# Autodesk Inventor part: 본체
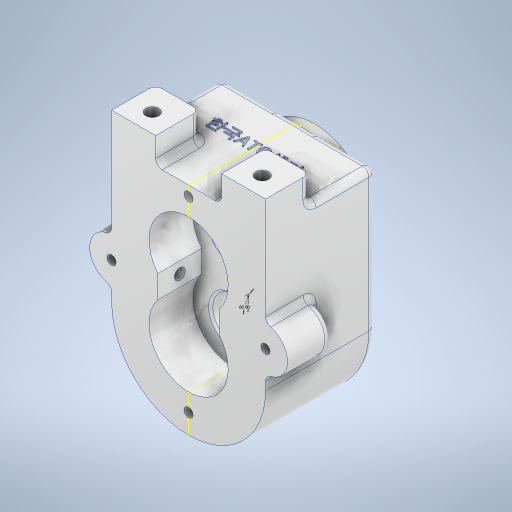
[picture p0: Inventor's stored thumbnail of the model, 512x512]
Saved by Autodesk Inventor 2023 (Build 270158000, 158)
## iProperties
Created: 2024-03
Part Number: 본체
Material: 알루미늄 6061
Document SubType Name: Modeling
Designer: asung
Density: 2.7 g/cm^3
Appearance: 알루미늄 - 평지
Author: asung
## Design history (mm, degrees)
sketch "스케치1"
  geometry: L1 (-35, 0)-(-35, 63.5); L2 (35, 0)-(35, 63.5); L3 (-35, 63.5)-(35, 63.5); A1 r 35 centre (0, 0) between (-35, 0) and (35, 0); 3 further points
  constraints: 6 end point, 2 point on circle, 2 tangent, 2 vertical, 1 centre point, 1 coincident, 1 horizontal
  dimensions: "d0" = 70 diameter of A1; "d2" = 70 distance of L3.start L3.end; "d3" = 63.5 distance from line of point (0, 0) L3; "d4" = 0 distance from line of L2.end L3; "d5" = 0 distance from line of L3.end L2; "d6" = 0 distance from line of L1.end L3
extrude "돌출1" new body sketch "스케치1" distance "d7" = 50; taper "d8" = 0 deg
sketch "스케치2"
  geometry: L1 (-35, 0)-(-35, 63.5) reference; L2 (-35, 63.5)-(35, 63.5) reference; L3 (35, 63.5)-(35, 0) reference; L4 (0, 0)-(0, 33); L5 (14, 11.314)-(14, 21.686); L6 (-14, 11.314)-(-14, 21.686); L7 (-35, 0)-(-35, 63.5) reference; L8 (-35, 63.5)-(35, 63.5) reference; L9 (35, 63.5)-(35, 0) reference; L10 (-25, 8)-(-25, 63.5); L11 (25, 8)-(25, 63.5); L12 (-17, 0)-(17, 0); A1 r 35 centre (0, 0) between (-35, 0) and (35, 0) reference; A2 r 18 centre (0, 0) between (-14, 11.314) and (14, 11.314); A3 r 18 centre (0, 33) between (14, 21.686) and (-14, 21.686); A4 r 35 centre (0, 0) between (-35, 0) and (35, 0) reference; A5 r 8 centre (-17, 8) between (-25, 8) and (-17, 0); A6 r 8 centre (17, 8) between (17, 0) and (25, 8); 1 further point
  constraints: 12 end point, 8 point on circle, 4 centre point, 4 parallel, 4 tangent, 2 coincident, 2 point on line, 1 horizontal, 1 vertical
  dimensions: "d9" = 36 diameter of A2; "d10" = 33 distance of L4.start L4.end; "d11" = 36 diameter of A3; "d12" = 14 distance between parallel lines of L4 L5; "d13" = 14 distance between parallel lines of L4 L6; "d137" = 25 distance between parallel lines of L4 L10; "d138" = 25 distance between parallel lines of L4 L11; "d139" = 8 radius of A5; "d140" = 8 radius of A6
extrude "돌출2" cut sketch "스케치2" distance "d14" = 20; taper "d15" = 0 deg
sketch "스케치4"
  geometry: L1 (-14, 21.686)-(-14, 11.314) reference; L2 (14, 11.314)-(14, 21.686) reference; L3 (-35, 0)-(-35, 63.5) reference; L4 (-35, 63.5)-(35, 63.5) reference; L5 (35, 63.5)-(35, 0) reference; L6 (-35, 63.5)-(-15, 63.5); L7 (-15, 63.5)-(-15, 75.5); L8 (-15, 75.5)-(-35, 75.5); L9 (-35, 75.5)-(-35, 63.5); L10 (35, 63.5)-(15, 63.5); L11 (15, 63.5)-(15, 75.5); L12 (15, 75.5)-(35, 75.5); L13 (35, 75.5)-(35, 63.5); A1 r 18 centre (0, 33) between (14, 21.686) and (-14, 21.686) reference; A2 r 18 centre (0, 0) between (-14, 11.314) and (14, 11.314) reference; A3 r 35 centre (0, 0) between (-35, 0) and (35, 0) reference; 5 further points
  constraints: 16 end point, 4 parallel, 2 horizontal, 2 midpoint, 2 perpendicular
  dimensions: "d16" = 30 distance of L11.end L7.end; "d20" = 20 distance of L7.end L8.end; "d21" = 20 distance of L12.end L11.end; "d22" = 12 distance between parallel lines of L4 L12
extrude "돌출3" join sketch "스케치4" distance "d23" = 20; taper "d24" = 0 deg
fillet "모깎기1" dims "d25" = 3
fillet "모깎기2" dims "d26" = 3
fillet "모깎기3" dims "d27" = 3
sketch "스케치5"
  geometry: L1 (-35, 0)-(-35, 75.5) reference; L2 (-35, 75.5)-(-15, 75.5) reference; L3 (-15, 75.5)-(-15, 66.5) reference; L4 (-12, 63.5)-(12, 63.5) reference; L5 (15, 66.5)-(15, 75.5) reference; L6 (15, 75.5)-(35, 75.5) reference; L7 (35, 75.5)-(35, 0) reference; L8 (-14, 21.686)-(-14, 11.314) reference; L9 (14, 11.314)-(14, 21.686) reference; L10 (0, 0)-(0, -26); L11 (-14, 16.5)-(14, 16.5); L12 (0, 33)-(0, 0); L13 (-35, 33)-(-35, 0); L14 (35, 33)-(35, 0); A1 r 3 centre (-12, 66.5) between (-15, 66.5) and (-12, 63.5) reference; A2 r 3 centre (12, 66.5) between (12, 63.5) and (15, 66.5) reference; A3 r 35 centre (0, 0) between (-35, 0) and (35, 0) reference; A4 r 18 centre (0, 33) between (14, 21.686) and (-14, 21.686) reference; A5 r 18 centre (0, 0) between (-14, 11.314) and (14, 11.314) reference; A6 r 10 centre (-35, 16.5) between (-35, 26.5) and (-35, 6.5); A7 r 10 centre (35, 16.5) between (35, 6.5) and (35, 26.5); 7 further points
  constraints: 10 end point, 6 midpoint, 4 point on circle, 4 point on line, 2 centre point, 2 horizontal alignment, 2 parallel, 2 vertical
  dimensions: "d28" = 26 distance of L10.start L10.end; "d29" = 35 distance between parallel lines of L12 L13; "d30" = 35 distance between parallel lines of L12 L14; "d31" = 10 radius of A6; "d32" = 10 radius of A7
extrude "돌출4" join sketch "스케치5" distance "d33" = 20; taper "d34" = 0 deg
fillet "모깎기4" dims "d35" = 3
fillet "모깎기5" dims "d36" = 3
sketch "스케치6"
  geometry: A1 r 10 centre (35, 16.5) between (37.308, 6.77) and (37.308, 26.23) reference; A2 r 10 centre (-35, 16.5) between (-37.308, 26.23) and (-37.308, 6.77) reference; 3 further points
  constraints: 2 coincident
hole "구멍1" sketch "스케치6" at (35, 16.5), (-35, 16.5) diameter "d37" = 4.134; stored, may be unused: countersink angle "d41" = 90 deg, drill point angle "d43" = 118 deg; dims "d38" = 10, "d39" = 7, "d40" = 3, "d42" = 12
sketch "스케치8"
  geometry: L1 (14, 21.686)-(14, 11.314) reference; L2 (-14, 11.314)-(-14, 21.686) reference; L3 (35, 0)-(35, 3.851) reference; L4 (35, 29.149)-(35, 75.5) reference; L5 (35, 75.5)-(15, 75.5) reference; L6 (15, 75.5)-(15, 66.5) reference; L7 (12, 63.5)-(-12, 63.5) reference; L8 (-15, 66.5)-(-15, 75.5) reference; L9 (-15, 75.5)-(-35, 75.5) reference; L10 (-35, 75.5)-(-35, 29.149) reference; L11 (-35, 3.851)-(-35, 0) reference; L12 (0, 0)-(0, -26); L13 (0, 33)-(0, 59); C1 r 2.067 at (35, 16.5) reference; C2 r 2.067 at (-35, 16.5) reference; A1 r 18 centre (0, 33) between (14, 21.686) and (-14, 21.686) reference; A2 r 18 centre (0, 0) between (-14, 11.314) and (14, 11.314) reference; A3 r 35 centre (0, 0) between (-35, 0) and (35, 0) reference; A4 r 3 centre (38, 3.851) between (37.308, 6.77) and (35, 3.851) reference; A5 r 10 centre (35, 16.5) between (37.308, 6.77) and (37.308, 26.23) reference; A6 r 3 centre (38, 29.149) between (35, 29.149) and (37.308, 26.23) reference; A7 r 3 centre (12, 66.5) between (12, 63.5) and (15, 66.5) reference; A8 r 3 centre (-12, 66.5) between (-15, 66.5) and (-12, 63.5) reference; A9 r 3 centre (-38, 29.149) between (-37.308, 26.23) and (-35, 29.149) reference; A10 r 10 centre (-35, 16.5) between (-37.308, 26.23) and (-37.308, 6.77) reference; A11 r 3 centre (-38, 3.851) between (-35, 3.851) and (-37.308, 6.77) reference; 1 further point
  constraints: 4 end point, 2 vertical
  dimensions: "d44" = 26 distance of L12.start L12.end; "d45" = 26 distance of L13.start L13.end
hole "구멍2" sketch "스케치8" at (0, -26), (0, 59) diameter "d46" = 4.134; stored, may be unused: countersink angle "d50" = 90 deg, drill point angle "d52" = 118 deg; dims "d47" = 10, "d48" = 4, "d49" = 2, "d51" = 12
sketch "스케치12"
  geometry: L1 (50, -43.392)-(0, -43.392) reference; L2 (0, -43.392)-(0, -22.627) reference; L3 (0, -22.627)-(20, -22.627) reference; L4 (20, -22.627)-(20, 0) reference; L5 (20, 0)-(0, 0) reference; L6 (0, 0)-(0, 10.373) reference; L7 (0, 10.373)-(20, 10.373) reference; L8 (20, 10.373)-(20, 33) reference; L9 (20, 33)-(0, 33) reference; L10 (0, 33)-(0, 52.95) reference; L11 (0, 52.95)-(17, 52.95) reference; L12 (21.472, 52.186)-(50, 52.186) reference; L13 (50, 52.186)-(50, -43.392) reference; L14 (20, 0)-(20, 10.373) reference; C1 r 2.5 at (10, 5.186); 2 further points
  constraints: 1 centre point, 1 horizontal alignment, 1 midpoint, 1 other
  dimensions: "d53" = 5 diameter of C1; "d54" = 10 distance of C1.centre point (0, 5.186)
extrude "돌출5" cut sketch "스케치12" distance "d55" = 10; taper "d56" = 0 deg
sketch "스케치15"
  geometry: L1 (-35, 63.5)-(35, 63.5) reference; L2 (35, 63.5)-(35, 0) reference; L3 (-35, 0)-(-35, 63.5) reference; L4 (0, 0)-(0, 33); C1 r 26 at (0, 33); A1 r 35 centre (0, 0) between (-35, 0) and (35, 0) reference; 1 further point
  constraints: 2 end point, 1 centre point, 1 coincident, 1 vertical
  dimensions: "d57" = 33 distance of L4.start L4.end; "d58" = 52 diameter of C1
extrude "돌출6" join sketch "스케치15" distance "d60" = 7.3; taper "d61" = 0 deg
sketch "스케치17"
  geometry: C1 r 26 at (0, 0) reference; C2 r 16 at (0, 0); 1 further point
  constraints: 1 centre point, 1 coincident
  dimensions: "d62" = 32 diameter of C2
extrude "돌출7" join sketch "스케치17" distance "d63" = 4; taper "d64" = 0 deg
fillet "모깎기6" dims "d65" = 3
sketch "스케치21"
  geometry: L1 (14, 21.686)-(14, 11.314) reference; L2 (-14, 11.314)-(-14, 21.686) reference; L3 (35, 0)-(35, 3.851) reference; L4 (35, 29.149)-(35, 75.5) reference; L5 (35, 75.5)-(15, 75.5) reference; L6 (15, 75.5)-(15, 66.5) reference; L7 (12, 63.5)-(-12, 63.5) reference; L8 (-15, 66.5)-(-15, 75.5) reference; L9 (-15, 75.5)-(-35, 75.5) reference; L10 (-35, 75.5)-(-35, 29.149) reference; L11 (-35, 3.851)-(-35, 0) reference; C1 r 2.067 at (0, -26) reference; C2 r 2.067 at (0, 59) reference; C3 r 2.067 at (35, 16.5) reference; C4 r 2.067 at (-35, 16.5) reference; C5 r 10 at (0, 33); C6 r 10 at (0, 0); A1 r 18 centre (0, 33) between (14, 21.686) and (-14, 21.686) reference; A2 r 18 centre (0, 0) between (-14, 11.314) and (14, 11.314) reference; A3 r 35 centre (0, 0) between (-35, 0) and (35, 0) reference; A4 r 3 centre (38, 3.851) between (37.308, 6.77) and (35, 3.851) reference; A5 r 10 centre (35, 16.5) between (37.308, 6.77) and (37.308, 26.23) reference; A6 r 3 centre (38, 29.149) between (35, 29.149) and (37.308, 26.23) reference; A7 r 3 centre (12, 66.5) between (12, 63.5) and (15, 66.5) reference; A8 r 3 centre (-12, 66.5) between (-15, 66.5) and (-12, 63.5) reference; A9 r 3 centre (-38, 29.149) between (-37.308, 26.23) and (-35, 29.149) reference; A10 r 10 centre (-35, 16.5) between (-37.308, 26.23) and (-37.308, 6.77) reference; A11 r 3 centre (-38, 3.851) between (-35, 3.851) and (-37.308, 6.77) reference; 1 further point
  constraints: 2 centre point, 2 coincident
  dimensions: "d91" = 20 diameter of C5; "d92" = 20 diameter of C6
extrude "돌출8" cut sketch "스케치21" distance "d93" = 10; taper "d94" = 0 deg
sketch "스케치22"
  geometry: L1 (-18, 50)-(-18, 30) reference; L2 (-18, 30)-(-10, 30) reference; L3 (-10, 30)-(-10, 20) reference; L4 (-10, 20)-(10, 20) reference; L5 (10, 20)-(10, 30) reference; L6 (10, 30)-(23, 30) reference; L7 (23, 30)-(23, 20) reference; L8 (43, 20)-(43, 30) reference; L9 (43, 30)-(51, 30) reference; L10 (51, 30)-(51, 50) reference; L11 (51, 50)-(56.933, 50) reference; L12 (56.933, 50)-(56.933, 38) reference; L13 (56.933, 38)-(59, 36.758) reference; L14 (59, 36.758)-(61.067, 38) reference; L15 (61.067, 38)-(61.067, 50) reference; L16 (61.067, 50)-(63.5, 50) reference; L17 (63.5, 50)-(63.5, 0) reference; L18 (63.5, 0)-(62, 0) reference; L19 (59, -3)-(59, -7.3) reference; L20 (59, -7.3)-(49, -7.3) reference; L21 (49, -7.3)-(49, -11.3) reference; L22 (49, -11.3)-(17, -11.3) reference; L23 (17, -11.3)-(17, -7.3) reference; L24 (17, -7.3)-(7, -7.3) reference; L25 (7, -7.3)-(7, -3) reference; L26 (4, 0)-(-35, 0) reference; L27 (-35, 0)-(-35, 50) reference; L28 (-35, 50)-(-28.067, 50) reference; L29 (-28.067, 50)-(-28.067, 38) reference; L30 (-28.067, 38)-(-26, 36.758) reference; L31 (-26, 36.758)-(-23.933, 38) reference; L32 (-23.933, 38)-(-23.933, 50) reference; L33 (-23.933, 50)-(-18, 50) reference; L34 (-10, 30)-(10, 30) reference; L35 (0, 30)-(0, 15.959); L36 (23, 20)-(43, 20) reference; L37 (7, 30)-(7, 20); L38 (0, 15.959)-(7, 20); L39 (7, 20)-(0, 20); A1 r 3 centre (62, -3) between (62, 0) and (59, -3) reference; A2 r 3 centre (4, -3) between (7, -3) and (4, 0) reference; 3 further points
  constraints: 8 end point, 2 midpoint, 2 point on line, 1 parallel, 1 vertical
  dimensions: "d143" = 7 distance between parallel lines of L35 L37; "d144" = 60 deg angle of L35 L38
  node "절단 모서리 투영9"
chamfer "모따기1" distance "d97" = 1; stored, may be unused: second distance "d98" = 2, angle "d99" = 45 deg
chamfer "모따기2" distance "d100" = 1; stored, may be unused: second distance "d101" = 2, angle "d102" = 45 deg
sketch "스케치24"
  geometry: C1 r 16 at (0, 0) reference; 2 further points
  constraints: 1 coincident
hole "구멍6" sketch "스케치24" at (0, 0) diameter "d103" = 15; stored, may be unused: countersink angle "d107" = 90 deg, drill point angle "d109" = 0 deg; dims "d104" = 8, "d105" = 25, "d106" = 7.3, "d108" = 31.5
chamfer "모따기3" distance "d110" = 1; stored, may be unused: second distance "d111" = 2, angle "d112" = 45 deg
fillet "모깎기7" dims "d113" = 3
fillet "모깎기8" dims "d114" = 3
sketch "스케치25" dims "d115" = 42
  geometry: C1 r 16 at (0, 0) reference; C2 r 26 at (0, 0) reference; 3 further points
  constraints: 1 coincident, 1 vertical alignment, 2 other
hole "구멍7" sketch "스케치25" at (0, 21) diameter "d116" = 3.242; stored, may be unused: countersink angle "d120" = 90 deg, drill point angle "d122" = 118 deg; dims "d117" = 8, "d118" = 25, "d119" = 7.3, "d121" = 10
sketch "스케치26"
  geometry: 1 further point
sketch "스케치27"
  geometry: 1 further point
sketch "스케치28"
  geometry: L1 (20, 17)-(20, 0) reference; L2 (20, 0)-(0, 0) reference; L3 (0, 0)-(0, 17) reference; L4 (3, 20)-(17, 20) reference; L5 (53, 20)-(67, 20) reference; L6 (70, 17)-(70, 0) reference; L7 (70, 0)-(50, 0) reference; L8 (50, 0)-(50, 17) reference; L9 (35, 50)-(35, 41.357); C1 r 3 at (10, 8.5); C2 r 3 at (60, 8.5); A1 r 3 centre (3, 17) between (3, 20) and (0, 17) reference; A2 r 3 centre (17, 17) between (20, 17) and (17, 20) reference; A3 r 3 centre (53, 17) between (53, 20) and (50, 17) reference; A4 r 3 centre (67, 17) between (70, 17) and (67, 20) reference; 1 further point
  constraints: 2 centre point, 2 end point, 1 midpoint, 1 symmetric about line, 1 vertical, 1 vertical alignment, 1 other
  dimensions: "d126" = 6 diameter of C1; "d127" = 8.5 distance from line of C1.centre L2
extrude "돌출9" cut sketch "스케치28" distance "d128" = 16; taper "d129" = 0 deg
sketch "스케치29"
  geometry: L1 (24, 0)-(0, 0) reference; 3 further points
  constraints: 1 midpoint, 1 other
  dimensions: "d130" = 30 vertical distance of point (12, 0) point (11.867, 30)
feature "엠보싱1" sketch "스케치29" dims "d0" = 70, "d2" = 70, "d3" = 63.5, "d4" = 0, "d5" = 0, "d6" = 0, "d131" = 0.5, "d132" = 0
chamfer "모따기4" distance "d134" = 1; stored, may be unused: second distance "d135" = 2, angle "d136" = 45 deg
revolve "회전3" stored, may be unused: angle "d145" = 90 deg
node "솔리드1"
mirror "미러1"
pattern_circular "원형 패턴2" dims angle "d124" = 360 deg
node "투영된 루프2"
node "투영된 루프4"
node "투영된 루프7"
node "투영된 루프9"
node "절단 모서리 투영1"
node "절단 모서리 투영3"
node "절단 모서리 투영4"
node "절단 모서리 투영5"
node "절단 모서리 투영8"
node "절단 모서리 투영10"
node "절단 모서리 투영11"
feature "A9D066F2-1C7D-4E18-AEED-F7BC21143FA4" dims "d46" = 4.134, "d47" = 10, "d48" = 4, "d49" = 2, "d50" = 90 deg, "d51" = 12, "d52" = 118 deg
